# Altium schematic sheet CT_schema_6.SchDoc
size 221 x 258 mm
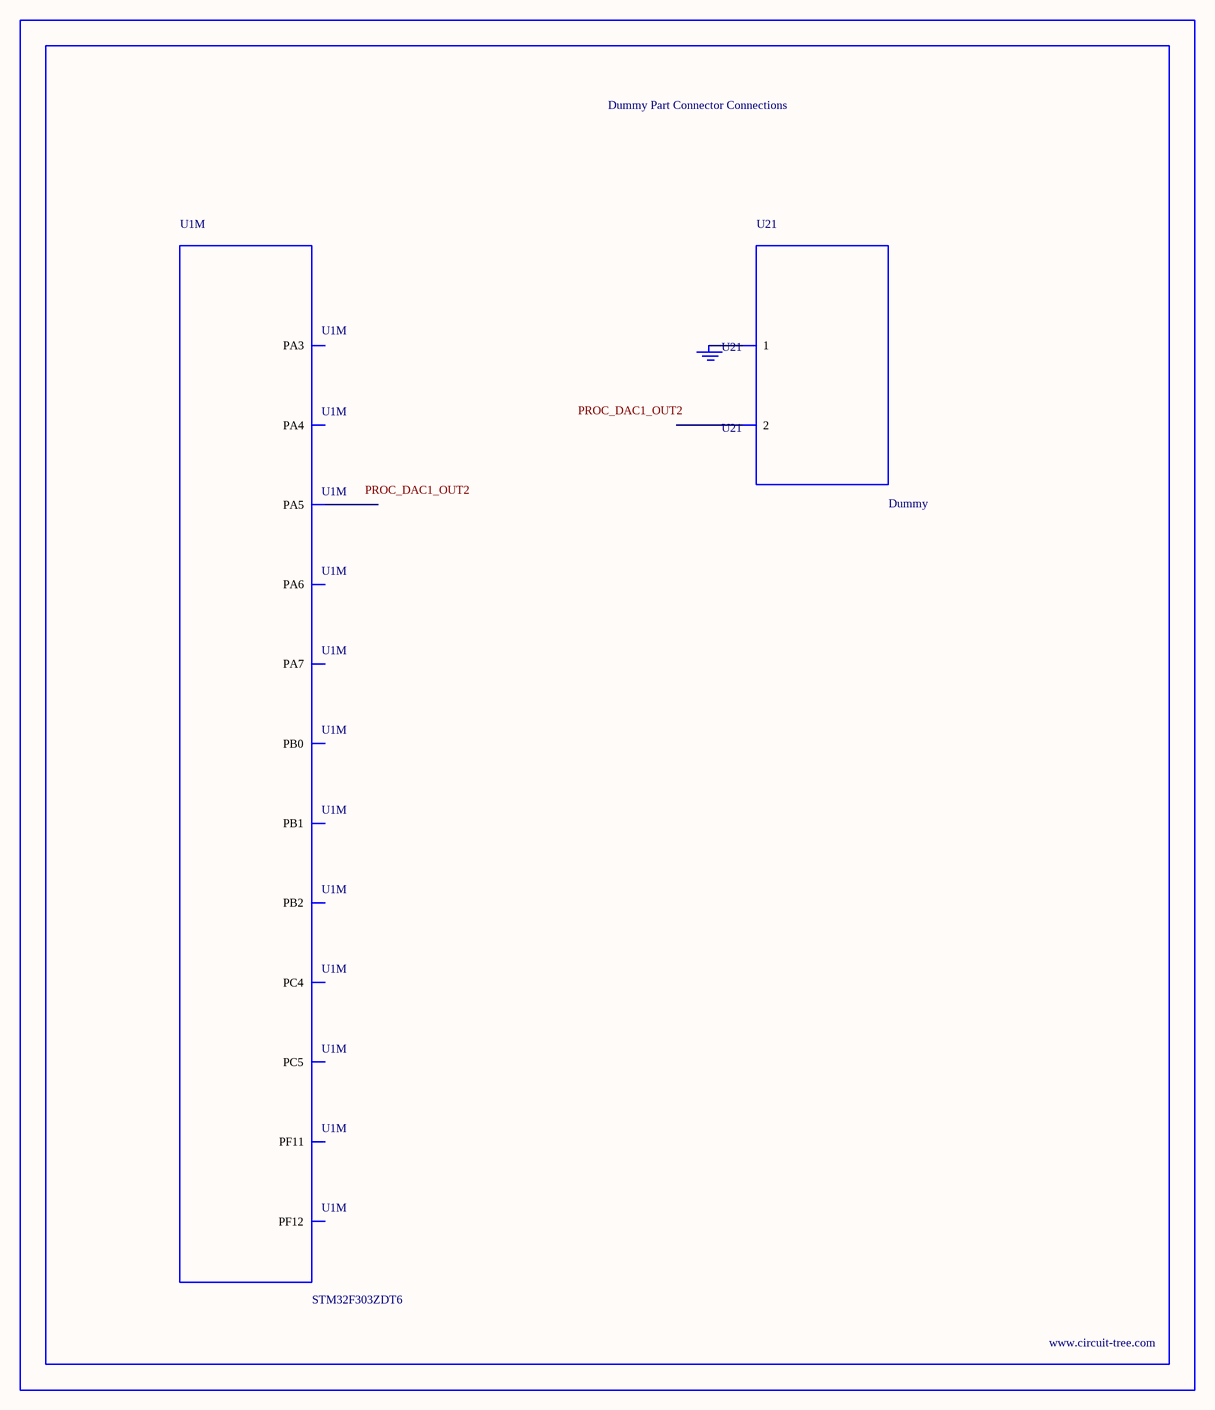
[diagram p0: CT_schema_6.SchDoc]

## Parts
BORDER5  (no value)
GND_INSTANCE_5_0  (no value)
U1  STM32F303ZDT6  [LQFP144]  (part M of 13)
U21  Dummy  [DUMMY_PACKAGE_190]

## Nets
NetGND_INSTANCE_5_0_0: GND_INSTANCE_5_0.0(GND) U21.1

Not connected (* = marked no-connect by the designer): U1 37(PA3) 40(PA4) 41(PA5) 42(PA6) 43(PA7) 44(PC4) 45(PC5) 46(PB0) 47(PB1) 48(PB2) 49(PF11) 50(PF12); U21 2

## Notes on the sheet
- Labels drawn without touching a wire or pin: PROC_DAC1_OUT2

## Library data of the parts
BORDER5 = BORDER_PAGE5
GND_INSTANCE_5_0 = GND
